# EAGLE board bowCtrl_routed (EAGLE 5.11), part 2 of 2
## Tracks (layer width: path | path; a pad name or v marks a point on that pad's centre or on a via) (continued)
RXIN  (via drill 0.5) (continued)
  Top 0.2: v95.88,23 97.08,23 C31.1 | X4.6 82.33,17.15 81.18,16 74.53,16 74.28,15.75 63.48,15.75 62.48,14.75 46.12,14.75 45.56,15.31 45.56,17.24 44.84,17.24 U$2.37
  Bottom 0.2: R82.1 97.23,23.05 97.23,23 v95.88,23 95.83,22.95 93.78,22.95 93.23,22.4 89.33,22.4 87.23,20.3 87.23,18.5 85.98,17.25 85.98,16.75 85.33,16.1 82.38,16.1 82.38,17.15 X4.6
RXIP  (via drill 0.5)
  Top 0.2: v95.83,25.6 C30.1 | U$2.40 46.33,18.35 46.33,17.2 46.08,16.95 46.08,15.91 46.84,15.15 53.43,15.15 56.53,18.25 83.83,18.25 84.88,17.2 X4.4
  Bottom 0.2: R81.1 97.28,25.6 v95.83,25.6 93.03,22.8 84.93,22.8 84.93,17.2 X4.4
S88_5V  (via drill 0.5)
  Top 1: v8.53,34.7 10.73,36.9 11.83,36.9 X1.1
  Bottom 1: JMP1.2 12.83,33.1 12.83,35.95 11.88,36.9 X1.1 | v8.53,34.7 8.53,22.75 11.83,19.45 X3.1
S88_CLK  (via drill 0.5)
  Top 0.2: v15.08,19.45 15.38,19.75 22.98,19.75 23.33,19.4 27.08,19.4 27.58,19.9 32.51,19.9 32.85,20.24 U$2.25
  Bottom 0.2: v15.08,19.45 15.43,19.8 15.43,22.2 14.43,23.2 X3.4 14.38,23.35 13.38,24.35 13.38,26.95 10.53,29.8 10.53,37.95 11.78,37.95 12.88,39.05 12.88,39.25 14.38,40.75 X1.4
S88_PS  (via drill 0.5)
  Top 0.2: 17.33,25.75 14.43,25.75 X3.6 | 17.33,25.75 18.53,25.75 18.53,23.3 19.73,22.1 26.53,22.1 27.38,21.25 U$2.23 | v17.33,43.25 14.43,43.25 X1.6 | 17.33,25.75 v17.33,25.8
  Bottom 0.2: v17.33,43.25 16.98,42.9 16.98,29.05 17.33,28.7 v17.33,25.8
S88_RAILD  (via drill 0.5)
  Top 0.2: v26.33,23.3 27.93,21.7 29.98,21.7 30.08,21.8 35.38,21.8 35.48,21.7 37.48,21.7 U$2.22 | v26.08,25.65 23.43,28.3 16.58,28.3 | 16.58,28.3 14.43,28.3 X3.8 | v16.58,45.45 14.78,45.45 14.43,45.8 X1.8 | 16.58,28.3 v16.58,28.35
  Bottom 0.2: v26.33,23.3 26.08,23.55 v26.08,25.65 | v16.58,28.35 v16.58,45.45
S88_RST  (via drill 0.5)
  Top 0.2: v13.53,22.2 14.33,22.2 14.83,21.7 26.28,21.7 27.23,20.75 U$2.24 | v7.88,41.05 10.23,43.4 10.68,43.4 11.83,44.55 X1.7 | v7.38,27.6 7.88,27.1 11.83,27.1 X3.7
  Bottom 0.2: v13.53,22.2 12.88,22.85 12.88,26.05 11.88,27.05 X3.7 | v7.88,41.05 7.48,40.65 7.48,27.7 v7.38,27.6
S88_RX  (via drill 0.5)
  Top 0.2: v23.88,24.05 26.68,24.05 28.63,22.1 29.78,22.1 29.93,22.25 33.68,22.25 34.73,23.3 36.28,23.3 36.33,23.25 U$2.19 | v17.73,38.05 17.58,38.2 14.43,38.2 X1.2
  Bottom 0.2: v23.88,24.05 22.33,25.6 20.13,25.6 20.13,35.65 v17.73,38.05
S88_TX  (via drill 0.5)
  Top 0.2: v29.43,22.85 29.63,22.65 33.48,22.65 34.53,23.7 37.48,23.7 U$2.18 | v26.73,20.15 26.38,20.5 14.63,20.5 14.43,20.7 X3.2
  Bottom 0.2: v26.73,20.15 v29.43,22.85
SENSE0  (via drill 0.5)
  Top 0.2: v28.38,42.85 30.58,45.05 31.63,45.05 31.98,44.7 45.63,44.7 45.73,44.6 U$3.28 | v27.18,39.65 16.28,39.65 16.18,39.75 13.03,39.75 11.78,41 v10.73,41 | R2.2 12.23,50.05 v12.28,50.05
  Bottom 0.2: v28.38,42.85 27.18,41.65 v27.18,39.65 | v10.73,41 9.78,41.95 9.78,48.55 R86.1 9.38,49.05 9.38,50.05 v12.28,50.05
SENSE1  (via drill 0.5)
  Top 0.2: v49.23,47.15 47.28,45.2 45.78,45.2 U$3.27 | v50.03,62.05 47.98,64.1 40.03,64.1 37.93,62 37.93,61.1 36.68,61.1 36.63,61.15 v34.08,61.15 | v33.03,57.15 32.68,57.5 16.38,57.5 15.88,57 15.88,53 16.38,53 17.03,52.35 17.03,49 R87.1 11.13,49.05 10.13,50.05 8.68,50.05 v8.03,50.7
  Bottom 0.2: v49.23,47.15 50.03,47.95 v50.03,62.05 | v34.08,61.15 33.03,60.1 v33.03,57.15 | R4.2 8.03,51.25 v8.03,50.7
SENSE2  (via drill 0.5)
  Top 0.2: v46.93,45.95 45.83,45.95 U$3.26 | v42.48,43.95 42.13,44.3 v31.28,44.3 | v31.13,50.8 21.63,50.8 R6.2 21.23,51.1 20.33,50.2 18.38,50.2 v18.18,50.4
  Bottom 0.2: v46.93,45.95 45.03,44.05 45.03,41.45 44.48,40.9 42.48,40.9 v42.48,43.95 | v31.28,44.3 31.13,44.45 v31.13,50.8 | v18.18,50.4 R88.1
SENSE3  (via drill 0.5)
  Top 0.2: v28.78,47.35 29.83,46.3 36.13,46.3 36.38,46.55 45.73,46.55 U$3.25 | 22.53,49.6 21.88,49.6 R89.1 | 22.53,49.6 v27.28,49.6 | v22.53,50 22.53,49.6
  Bottom 0.2: v28.78,47.35 27.28,48.85 v27.28,49.6 | R8.2 20.33,50.5 20.33,50.35 20.63,50.05 22.53,50.05 v22.53,50
SENSE4  (via drill 0.5)
  Top 0.2: v35.68,47.15 U$3.24 | v35.78,50.35 34.88,51.25 R10.2
  Bottom 0.2: v35.68,47.15 35.78,47.25 v35.78,50.35
SENSE5  (via drill 0.5)
  Top 0.2: v35.03,48.85 35.08,48.85 36.23,47.7 45.63,47.7 U$3.23
  Bottom 0.2: v35.03,48.85 32.78,51.1 R12.2
SENSE6  (via drill 0.5)
  Top 0.2: v44.13,48.45 U$3.22 | v44.68,51.4 44.53,51.25 R14.2
  Bottom 0.2: v44.13,48.45 44.68,49 v44.68,51.4
SENSE7  (via drill 0.5)
  Top 0.2: v43.03,48.85 43.38,49.2 45.68,49.2 45.73,49.15 U$3.21
  Bottom 0.2: v43.03,48.85 41.68,50.2 R16.2
SENSE8
  Top 0.2: R18.2 58.08,51.1 56.23,49.25 53.58,49.25 U$3.18
SENSE9  (via drill 0.5)
  Top 0.2: U$3.17 53.48,48.5 57.29,48.5 v57.85,49.06
  Bottom 0.2: v57.85,49.06 56.48,50.43 R20.2
SENSE10
  Top 0.2: R22.2 67.78,51.1 66.88,50.2 64.97,50.2 63.46,51.71 60.7,51.71 58.91,49.91 58.91,48.62 58.03,47.75 53.53,47.75 53.48,47.8 U$3.16
SENSE11  (via drill 0.5)
  Top 0.2: v62.78,47.15 53.48,47.15 U$3.15
  Bottom 0.2: v62.78,47.15 65.93,50.3 R24.2
SENSE12  (via drill 0.5)
  Top 0.2: v67.53,45.05 63.78,45.05 62.28,46.55 53.48,46.55 U$3.14 | v70.53,49.8 70.93,50.2 79.58,50.2 80.48,51.1 R26.2
  Bottom 0.2: v67.53,45.05 68.28,45.8 68.28,47.55 v70.53,49.8
SENSE13  (via drill 0.5)
  Top 0.2: v51.53,47.3 52.83,46 53.33,46 53.43,45.9 U$3.13 | v51.53,55.3 53.78,57.55 59.68,57.55 v62.73,54.5 | v77.48,50.95 70.58,50.95 69.43,49.8 63.73,49.8 63.38,50.15 v63.38,50.33
  Bottom 0.2: v51.53,47.3 v51.53,55.3 | v62.73,54.5 63.38,53.85 v63.38,50.33 | v77.48,50.95 78.88,50.95 R28.2
SENSE14  (via drill 0.5)
  Top 0.2: v52.28,45.35 53.33,45.35 53.43,45.25 U$3.12 | v38.28,78.8 38.33,78.85 83.83,78.85 86.78,75.9 88.28,75.9 v90.68,73.5 | v93.93,54.6 R30.2
  Bottom 0.2: v38.28,78.8 48.98,78.8 51.73,76.05 51.73,73.35 52.28,72.8 v52.28,45.35 | v90.68,73.5 90.68,72 91.98,70.7 92.33,70.7 92.33,67.7 93.93,66.1 v93.93,54.6
SENSE15  (via drill 0.5)
  Top 0.2: v58.58,45.8 55.28,45.8 54.18,44.7 53.58,44.7 U$3.11 | v59.88,47.9 61.23,47.9 61.54,48.21 70.48,48.21 71.42,47.27 82.4,47.27 85.13,50 v87.73,50
  Bottom 0.2: v87.73,50 R32.2 | v58.58,45.8 59.88,47.1 v59.88,47.9
SERV0  (via drill 0.5)
  Top 0.2: LED1.C 6.83,69.85 6.63,69.65 R65.1 4.98,69.6 4.53,69.6 v3.88,68.95 | v32.83,30.95 36.03,27.75 U$2.10 | v26.53,59.45 23.83,62.15 20.78,62.15 18.63,64.3 v1.33,64.3
  Bottom 0.2: v32.83,30.95 29.13,34.65 29.13,45.9 26.53,48.5 v26.53,59.45 | v1.33,64.3 0.88,64.75 0.88,65.95 v3.88,68.95
SERV1  (via drill 0.5)
  Top 0.2: LED3.C 11.73,69.65 R66.1 10.08,69.7 9.28,69.7 9.28,72 10.63,73.35 19.43,73.35 19.43,70.75 19.63,70.55 22.83,70.55 22.83,69.35 23.03,69.15 23.98,69.15 v24.48,68.65 | v24.18,32.85 25.73,31.3 31.28,31.3 35.33,27.25 U$2.11
  Bottom 0.2: v24.18,32.85 22.03,35 22.03,42.75 21.68,43.1 21.38,43.1 21.38,45.1 22.58,46.3 22.58,47.75 24.28,49.45 24.28,62.5 24.48,62.7 v24.48,68.65
SERV2  (via drill 0.5)
  Top 0.2: LED5.C 16.98,69.85 16.78,69.65 R67.1 14.73,69.15 11.83,69.15 v11.03,68.35 | v23.08,32.85 25.03,30.9 30.88,30.9 35.03,26.75 U$2.12 | v16.28,52 13.43,54.85 13.43,58.7 v10.83,58.7
  Bottom 0.2: v16.28,52 16.28,51.2 18.38,49.1 18.38,47.25 18.13,47 18.13,43.1 18.43,43.1 18.78,42.75 18.78,41.25 20.53,39.5 20.53,32.85 v23.08,32.85 | v10.83,58.7 11.03,58.9 v11.03,68.35
SERV3  (via drill 0.5)
  Top 0.2: R68.1 21.88,69.65 22.08,69.85 LED7.C 22.18,69.8 22.28,69.8 v22.28,68.65 | v34.43,26.25 U$2.13 | v37.18,61.85 36.88,62.15 33.93,62.15 31.68,64.4 v21.68,64.4 | v81.47,30.85 81.68,31.06 95.74,31.06 v95.79,31.11 | v20.67,67.01 97.79,67.01 v98.51,67.73
  Bottom 0.2: v34.43,26.25 34.38,26.3 34.38,35.5 35.48,36.6 35.48,45.85 36.58,46.95 36.58,55.05 36.78,55.25 36.78,61.45 v37.18,61.85 | v21.68,64.4 21.23,64.85 21.23,67.01 | 21.23,67.01 21.23,67.6 v22.28,68.65 | 21.23,67.01 v20.67,67.01 | R100.2 81.47,32.75 v81.47,30.85 | v95.79,31.11 95.79,42.43 97.78,44.42 97.78,60.64 99.77,62.63 99.77,66.47 v98.51,67.73
SERV4  (via drill 0.5)
  Top 0.2: R69.1 29.98,69.65 LED9.C 31.18,68.85 34.88,68.85 v35.48,68.25 | v41.58,36.5 41.83,36.5 U$2.95
  Bottom 0.2: v41.58,36.5 40.03,38.05 40.03,42.15 39.28,42.9 39.28,56.4 37.88,57.8 37.88,61.45 37.93,61.5 37.93,65.8 v35.48,68.25
SERV5  (via drill 0.5)
  Top 0.2: LED11.C 35.23,69.85 35.03,69.65 R70.1 33.38,69.7 32.58,69.7 32.58,72.8 32.03,73.35 28.83,73.35 27.53,72.05 27.53,70.4 v26.93,69.8 | v40.48,36.5 41.23,35.75 41.33,35.75 U$2.96 | v39.28,38.8 39.18,38.9 v31.28,38.9 | v30.28,51.55 25.08,56.75 v25.03,56.75
  Bottom 0.2: v40.48,36.5 39.28,37.7 v39.28,38.8 | v30.28,51.55 30.28,44.05 31.28,43.05 v31.28,38.9 | v25.03,56.75 25.38,57.1 25.38,63.75 26.93,65.3 v26.93,69.8
SERV6  (via drill 0.5)
  Top 0.2: LED13.C 40.13,69.65 R71.1 38.63,69.6 v38.63,68.5 | v39.38,36.5 39.83,36.05 U$2.99 | v38.53,56.05 38.53,57.35 v39.43,57.35 39.18,57.4 40.53,58.75 42.58,58.75 42.58,59.3 44.43,61.15 50.23,61.15 51.13,62.05 60.43,62.05 63.63,58.85 71.18,58.85 v71.28,58.75 | v74.98,44.9 73.47,46.41 v71.29,46.41
  Bottom 0.2: v39.38,36.5 38.53,37.35 v38.53,56.05 | v39.43,57.35 39.38,57.4 39.38,59.15 38.88,59.65 38.88,68.25 v38.63,68.5 | R99.2 78.03,35.75 78.03,35.9 77.73,36.2 76.18,36.2 75.68,36.7 74.98,36.7 v74.98,44.9 | v71.29,46.41 v71.28,46.42 71.83,46.97 71.83,58.2 v71.28,58.75
SERV7  (via drill 0.5)
  Top 0.2: LED15.C 45.38,69.85 45.18,69.65 R72.1 43.13,69.15 40.73,69.15 39.14,67.56 37.81,67.56 v37.43,67.94 | v38.08,36.5 38.08,35.35 U$2.100 | v37.53,57.05 v38.63,58.15
  Bottom 0.2: v38.08,36.5 37.43,37.15 37.43,37.5 36.98,37.95 36.98,54.85 37.53,55.4 v37.53,57.05 | v38.63,58.15 38.33,58.45 38.33,67.04 v37.43,67.94
SERV8  (via drill 0.5)
  Top 0.2: R73.1 53.28,69.65 53.48,69.85 LED17.C 53.58,69.9 53.98,69.9 v53.98,71.05 | v61.68,27.75 53.23,27.75 U$2.66 | v61.83,59.55 60.08,61.3 v57.38,61.3
  Bottom 0.2: v61.68,27.75 61.83,27.9 v61.83,59.55 | v57.38,61.3 55.88,62.8 55.88,67.55 54.23,69.2 54.23,70.8 v53.98,71.05
SERV9  (via drill 0.5)
  Top 0.2: R74.1 58.38,69.65 LED19.C 59.78,68.65 v63.78,68.65 | v59.53,32.75 59.88,32.4 74.23,32.4 74.98,33.15 74.98,33.95 v75.13,33.95 | U$2.67 53.23,28.2 58.63,28.2 v58.93,28.5 | v70.08,41.7 70.08,41 v57.43,41
  Bottom 0.2: v75.13,33.95 79.73,33.95 79.73,36.3 R98.2 | v63.78,68.65 68.33,64.1 70.6,64.1 71.42,63.28 71.42,59.89 72.23,59.08 72.23,45.9 70.08,43.75 v70.08,41.7 | v57.43,41 57.58,40.85 57.58,35.2 59.48,33.3 59.48,32.8 v59.53,32.75 59.53,31.85 58.93,31.25 v58.93,28.5
SERV10  (via drill 0.5)
  Top 0.2: R75.1 63.43,69.65 63.63,69.85 LED21.C 63.73,69.8 v64.88,68.65 | v56.03,29.45 55.68,29.8 54.08,29.8 54.03,29.75 53.23,29.75 U$2.70 | v58.43,32.95 59.53,34.05 70.58,34.05 71.48,34.95 71.68,34.95 72.43,35.7 72.43,40.05 74.23,40.05 74.98,40.8 74.98,42.25 v76.33,43.6
  Bottom 0.2: v56.03,29.45 58.43,31.85 v58.43,32.95 | v64.88,68.65 64.88,68.6 71.93,68.6 73.79,66.74 73.79,47.86 76.33,45.32 v76.33,43.6
SERV11  (via drill 0.5)
  Top 0.2: R76.1 68.53,69.65 LED23.C 68.83,69.8 69.78,68.85 84.08,68.85 v84.78,68.15 | U$2.71 53.23,30.2 58.83,30.2 59.83,31.2 64.38,31.2 66.28,29.3 78.57,29.3 80.33,31.06 80.33,32.84 v84.51,32.84
  Bottom 0.2: v84.51,32.84 84.78,33.11 v84.78,68.15
SERV12  (via drill 0.5)
  Top 0.2: LED25.C 76.28,69.85 76.08,69.65 R77.1 74.48,69.6 v73.33,69.6 | v43.38,31.45 43.38,34.05 U$2.92 | v42.73,21.3 39.58,21.3 37.96,19.68 35.71,19.68 33.23,17.2 v25.83,17.2 | v25.83,13.9 27.53,12.2 35.33,12.2 36.43,11.1 36.43,9.65 36.03,9.65 35.28,8.9 35.28,7.35 38.48,7.35 38.93,6.9 38.93,5.1 v38.08,5.1 | v55.18,4.6 55.48,4.9 56.93,4.9 57.78,4.05 v57.78,3.7 | v81.43,23.15 80.53,22.25 64.93,22.25 63.18,20.5 v57.48,20.5
  Bottom 0.2: v43.38,31.45 44.03,30.8 44.03,22.6 v42.73,21.3 | v25.83,13.9 v25.83,17.2 | v38.08,5.1 55.18,5.1 v55.18,4.6 | v57.78,3.7 57.68,3.8 57.68,20.3 v57.48,20.5 | v81.43,23.15 82.43,24.15 82.43,42.5 81.68,43.25 80.63,43.25 | 80.63,43.25 79.73,43.25 79.73,40.45 R97.2 | 80.63,43.25 80.63,45.65 81.13,46.15 81.13,50 76.12,50 74.72,51.4 74.72,68.21 v73.33,69.6
SERV13  (via drill 0.5)
  Top 0.2: LED27.C 81.38,69.85 81.18,69.65 R78.1 79.53,69.7 78.73,69.7 78.73,72.75 78.13,73.35 38.63,73.35 37.68,72.4 37.68,69.35 35.83,67.5 31.57,67.5 v31.09,67.98 | v42.78,36.5 43.83,36.5 U$2.91 | v40.78,38.8 39.93,39.65 v34.33,39.65 | v33.08,49.3 32.33,50.05 v28.78,50.05
  Bottom 0.2: v42.78,36.5 40.78,38.5 v40.78,38.8 | v34.33,39.65 33.53,40.45 33.53,48.85 v33.08,49.3 | v28.78,50.05 28.68,50.15 28.68,65.45 31.09,67.86 v31.09,67.98
SERV14  (via drill 0.5)
  Top 0.2: LED29.C 86.28,69.65 R79.1 84.63,69.7 83.83,69.7 83.83,72.75 82.83,73.75 68.63,73.75 66.48,75.9 50.18,75.9 v49.93,76.15 | v36.68,36.9 37.03,37.25 44.33,37.25 U$2.90 | v36.23,45.45 36.58,45.8 v44.58,45.8
  Bottom 0.2: v36.68,36.9 36.23,37.35 v36.23,45.45 | v44.58,45.8 48,49.22 48,54.54 48.88,55.42 48.88,62.15 49.98,63.25 49.98,67.85 51.23,69.1 51.23,75.5 50.58,76.15 v49.93,76.15
SERV15  (via drill 0.5)
  Top 0.2: LED31.C 91.53,69.85 91.33,69.65 90.31,69.65 | 90.31,69.65 R80.1 | v45.08,36.5 44.88,36.5 44.88,34.1 U$2.89 | v80.38,49.25 v85.53,54.4 | v77.01,48.2 71.68,48.2 71.04,48.84 62.46,48.84 62.26,49.04 v59.86,49.05 | v53.69,52.02 48.99,52.02 v48.96,52.05 | v89.77,68.27 89.77,69.11 90.31,69.65
  Bottom 0.2: v45.08,36.5 47.78,39.2 47.78,39.75 46.68,40.85 46.13,40.85 45.53,41.45 45.53,43.9 46.53,44.9 47.03,44.9 47.78,45.65 47.78,48.4 48.96,49.58 v48.96,52.05 | R96.2 79.33,42.3 79.33,48.2 | 79.33,48.2 v80.38,49.25 | v85.53,54.4 85.28,54.65 85.28,63.2 86.78,64.7 88.88,64.7 88.88,67.38 v89.77,68.27 | v77.01,48.2 79.33,48.2 | v53.69,52.02 54.26,51.45 54.26,50.59 57.25,47.6 58.41,47.6 v59.86,49.05
SPI_A0  (via drill 0.5)
  Top 0.2: v37.18,64.4 37.28,64.5 66.08,64.5 69.43,61.15 v72.86,61.15 | v69.83,26.3 68.98,25.45 v68.33,25.45 | v68.33,9.1 68.33,7.55 65.63,7.55 v65.18,7.1 | U$2.29 40.83,19.15 39.03,19.15 38.47,18.59 38.47,18.37 38.1,18 v35.23,18 | v35.13,34.75 30.68,34.75 v29.93,35.5
  Bottom 0.2: v35.23,18 35.13,18.1 35.13,25.85 35.18,25.9 35.18,28.6 35.13,28.65 v35.13,34.75 | v37.18,64.4 30.18,64.4 29.08,63.3 29.08,56.35 29.53,55.9 29.53,39.5 29.53,38.3 29.53,35.9 v29.93,35.5 | v69.83,26.3 69.83,26.75 71.08,26.75 72.68,28.35 72.68,43.8 73.23,44.35 73.23,60.78 v72.86,61.15 | v68.33,25.45 v68.33,9.1 | v65.18,7.1 64.88,6.8 64.88,4.1 64.18,3.4 U$1.38
SPI_CS_ADC  (via drill 0.5)
  Top 0.2: v55.38,33.7 54.58,32.9 52.43,32.9 52.43,30.95 52.63,30.75 U$2.72 | v51.63,40.55 51.63,42.8 46.38,42.8 46.23,42.65 45.78,42.65 U$3.31
  Bottom 0.2: v55.38,33.7 55.33,33.75 55.33,36.8 54.23,37.9 54.23,38.35 52.03,40.55 v51.63,40.55
SPI_CS_DOGM  (via drill 0.5)
  Top 0.2: v55.63,30.95 55.38,31.2 53.23,31.2 U$2.73 | v59.73,10.1 61.73,8.1 67.33,8.1 v67.53,8.3
  Bottom 0.2: v55.63,30.95 55.28,30.6 55.28,23.8 59.73,19.35 v59.73,10.1 | v67.53,8.3 68.33,7.5 68.33,5.75 69.18,4.9 69.18,3.4 U$1.40
SPI_CS_SD  (via drill 0.5)
  Top 0.2: v66.63,30.05 65.08,31.6 58.98,31.6 58.88,31.7 53.23,31.7 U$2.74
  Bottom 0.2: JP33.8 63.93,9.1 64.88,10.05 64.88,12.6 66.23,12.6 67.43,13.8 67.43,17.85 66.63,18.65 v66.63,30.05
SPI_SCLK  (via drill 0.5)
  Top 0.2: 40.38,18.35 U$2.28 40.38,18.3 40.38,17.6 v40.83,17.15 | JP33.7 66.43,9.1 65.43,10.1 64.08,10.1 63.33,10.85 v61.68,10.85 57.63,10.85 56.98,11.5 45.33,11.5 v45.03,11.2 | v50.88,42.05 45.83,42.05 U$3.32 | v55.48,44.8 63.43,44.8 64.18,44.05 v64.28,44.05
  Bottom 0.2: v50.88,42.05 53.63,44.8 v55.48,44.8 | v64.28,44.05 63.93,43.7 63.93,39.65 64.38,39.2 64.38,25.15 65.73,23.8 65.73,20.95 64.83,20.05 63.78,20.05 61.53,17.8 61.53,10.85 | 61.53,10.85 61.53,8.15 61.98,7.7 61.98,3.75 61.63,3.4 U$1.37 | v61.68,10.85 61.53,10.85 | v40.83,17.15 45.03,12.95 v45.03,11.2
SPI_SDI  (via drill 0.5)
  Top 0.2: v37.98,10.1 41.53,6.55 56.03,6.55 59.03,3.55 59.03,3.4 U$1.36 58.68,4 60.28,5.6 65.48,5.6 66.38,6.5 JP33.9 66.48,6.6 67.98,6.6 v69.08,7.7 | U$2.31 41.83,19.2 41.38,19.2 41.03,19.55 38.78,19.55 38.09,18.86 v37.7,18.86 | v48.53,41.3 45.78,41.3 U$3.33 | v71.5,67.82 v51.15,67.82
  Bottom 0.2: v48.53,41.3 50.78,43.55 50.78,67.45 v51.15,67.82 | v69.08,7.7 69.08,29.3 71.13,29.3 72.28,30.45 72.28,44 72.63,44.35 72.63,59.76 72.03,60.36 72.03,63.55 71.5,64.08 v71.5,67.82 | v37.98,10.1 37.98,12.25 37.44,12.79 37.44,18.6 v37.7,18.86
SPI_SDO  (via drill 0.5)
  Top 0.2: 47.68,40.55 47.68,40.65 45.78,40.65 U$3.34 | 47.68,40.55 47.68,38.9 46.33,37.55 45.13,37.55 45.03,37.65 36.33,37.65 35.98,37.3 26.78,37.3 25.63,36.15 19.03,36.15 18.38,35.5 v15.83,35.5 | 41.33,18.35 U$2.30 41.33,18.25 41.33,17.85 41.58,17.6 41.58,16.4 32.83,16.4 32.78,16.35 32.78,14.65 15.78,14.65 15.28,15.15 v15.28,16.39 | v61.23,7.35 63.13,7.35 63.88,6.6 JP33.10 | v54.63,44.05 v56.88,44.05 | v49.63,41.3 48.88,40.55 47.68,40.55
  Bottom 0.2: v15.83,35.5 15.83,27.75 15.93,27.75 16.43,27.25 16.43,25.5 16.68,25.25 16.68,19.6 16.43,19.35 16.43,17.54 v15.28,16.39 | v61.23,7.35 60.93,7.65 60.93,19.8 56.88,23.85 56.88,26.55 57.63,27.3 58.83,27.3 59.73,28.2 59.73,28.7 60.93,29.9 60.93,33.75 59.13,35.55 59.13,38.2 58.18,39.15 58.18,41.35 56.88,42.65 v56.88,44.05 | v54.63,44.05 51.88,41.3 v49.63,41.3
TCK  (via drill 0.5)
  Top 0.2: v49.68,36.45 49.38,36.45 49.38,34.1 U$2.80 | v54.58,35.85 55.23,35.2 v67.68,35.2
  Bottom 0.2: v49.68,36.45 50.93,37.7 52.58,37.7 52.58,36.85 52.63,36.8 52.63,36.55 53.33,35.85 v54.58,35.85 | v67.68,35.2 71.28,31.6 JTAG1.9
TDI  (via drill 0.5)
  Top 0.2: v46.98,29.95 50.33,33.3 50.33,34.05 U$2.78 | v69.83,20.9 64.98,20.9 63.43,19.35 52.33,19.35 51.13,20.55 50.48,20.55 47.98,23.05 v46.98,23.05
  Bottom 0.2: v46.98,23.05 v46.98,29.95 | v69.83,20.9 70.28,21.35 70.28,24.75 71.28,25.75 JTAG1.5
TDO  (via drill 0.5)
  Top 0.2: v51.88,36.45 51.38,35.95 50.88,35.95 50.88,34.1 U$2.77 | v54.58,34.75 54.88,34.45 69.83,34.45 71.28,35.9 JTAG1.13
  Bottom 0.2: v51.88,36.45 52.23,36.1 52.48,36.1 53.83,34.75 v54.58,34.75
TMS  (via drill 0.5)
  Top 0.2: v58.33,37.85 56.88,37.85 56.48,37.45 51.78,37.45 50.03,35.7 49.88,35.7 49.88,34.1 U$2.79 | JTAG1.7 71.28,28.35 66.63,28.35 64.53,30.45 v60.18,30.45
  Bottom 0.2: v60.18,30.45 60.28,30.55 60.28,33.6 58.33,35.55 v58.33,37.85
TXON  (via drill 0.5)
  Top 0.2: U$2.46 49.38,18.4 49.38,19.3 49.48,19.4 49.48,20.1 48.63,20.95 47.98,20.95 46.23,22.7 46.23,23.4 46.93,24.1 48.18,24.1 52.53,19.75 63.18,19.75 65.08,21.65 86.17,21.65 86.17,20.8 | 86.13,19.75 X4.3 86.17,20.8 | C33.1 97.08,20.7 96.98,20.8 v95.88,20.8 86.17,20.8
  Bottom 0.2: v95.88,20.8 97.23,20.8 R84.1
TXOP  (via drill 0.5)
  Top 0.2: v47.83,15.9 47.83,18.35 U$2.43 | v47.68,13.2 48.03,13.55 62.58,13.55 63.33,12.8 66.43,12.8 68.48,14.85 75.28,14.85 75.93,15.5 77.18,15.5 77.43,15.25 84.48,15.25 86.38,17.15 86.38,18.65 87.63,18.65 88.68,19.7 X4.1 88.78,19.7 95.73,19.7 95.88,19.55 | 95.88,19.55 97.03,18.4 C32.1 | 95.88,19.55 v96.03,19.7
  Bottom 0.2: v47.83,15.9 47.68,15.75 v47.68,13.2 | v96.03,19.7 R83.1
V2_5  (via drill 0.6)
  Top 0.254: U$2.14 39.07,25.74 v39.18,25.85 | U$2.7 38.94,29.24 40.18,28 | U$2.62 v51.68,25.75 | 45.34,21.34 U$2.38 | 45.34,31.59 U$2.88
  Top 0.61: 40.18,25.85 40.18,28
  Top 1.016: v39.18,25.85 40.18,25.85 40.83,25.85 C22.+ | C22.+ 45.34,21.34 | 44.14,25.75 v51.68,25.75 | C22.+ 44.14,25.75 | 45.34,31.59 44.14,30.39 44.14,25.75
  Bottom 1.016: C21.1 v39.18,25.85 | 42.18,25 42.53,24.65 C22.+ | v51.68,25.75 52.03,25.85 C29.1
  other vias: 42.53,24.14
V3_3  (via drill 0.5, 0.6)
  Top 0.2: U$2.36 44.34,16.74 v44.76,16.32
  Top 0.254: U$2.83 U$2.84 47.34,34.84 v46.93,35.25 | U$2.3 38.17,31.24 39.31,32.38 40.34,33.41 U$2.98 | U$2.8 36.19,28.74 v35.93,29 | U$2.93 42.84,35.09 v42.68,35.25 | U$2.81 48.84,34.84 v48.43,35.25 | U$2.68 54.17,28.74 v54.43,29 | U$2.56 54.17,22.74 v54.43,23 | U$2.32 42.34,17.19 v42.43,17.1 | U$2.44 48.34,17.69 v48.93,17.1 | U$2.20 36.17,22.74 v35.93,22.5 | U$3.5 C55.1 | U$3.29 43.74,43.91 C54.1 | U$3.36 43.93,39.36 43.72,39.36 C56.1 | U$4.2 66.43,39.12 v66.43,38.25
  Top 0.406: v43.93,38.85 43.93,39.36
  Top 1: v85.58,29.8 v95.38,29.8 95.43,29.35 95.43,26.85 v90.18,21.6 | v33.53,18.65 33.38,18.8 30.28,18.8 OK1.8 29.83,18.6 v24.93,18.6 | v15.03,31.3 15.68,30.65 v17.78,30.65 | v19.33,25.45 19.33,23.65 19.88,23.65 v20.63,22.9 | v34.88,14.2 v36.48,14.2 36.93,14.45 37.88,15.4 42.38,15.4 42.38,17 v42.43,17.1 | U$1.34 54.03,3.4 56.48,3.4 U$1.35 | v56.13,40.6 55.03,40.6 C55.1 | v56.78,36.7 64.83,36.7 66.33,38.2 v66.43,38.25 | 62.33,12 57.63,12 v56.88,12.75 | 62.33,12 63.53,12 63.88,11.65 JP33.6 | v76.38,20.6 74.83,19.05 v64.28,19.05 | 62.33,12 v62.33,12.6
  Top 1.016: v37.68,33.25 38.43,33.25 39.31,32.38 42.43,29.25 C48.+ | C56.1 C54.1
  Bottom 0.2: 44.92,17.1 44.72,16.9 | 44.41,17.1 44.85,16.66
  Bottom 0.254: 36.43,29 v35.93,29 | C20.+ 92.18,7.75 92.43,8 92.43,12 R101.2 | v35.93,22.5 36.43,23 36.43,23.25 | v66.43,38.25 68.98,38.25 C57.1
  Bottom 1: 85.97,11.67 86.43,12.1 86.43,12.15 v86.73,12.45 88.13,13.85 C34.1 87.88,14.3 87.48,14.7 87.48,17.15 X4.2 87.93,17.4 90.18,17.4 v90.18,21.6 | R83.2 98.93,18.5 98.93,20.25 R84.2 98.98,20.8 98.98,23.05 R82.2 98.98,23.5 R81.2 98.78,25.95 98.63,26.1 98.63,26.55 v95.38,29.8 | 83.28,21.2 83.58,21.2 83.58,19.75 X4.5 | 83.28,21.2 80.48,21.2 80.03,20.75 78.83,20.75 C35.1 78.28,20.6 v76.38,20.6 | 83.28,29.8 R116.1 | 83.28,21.2 83.28,29.8 | 83.28,29.8 v85.58,29.8 | v33.53,18.65 33.53,15.75 C68.2 34.13,15.5 34.88,14.75 v34.88,14.2 | JMP1.3 15.03,32.6 v15.03,31.3 | v17.78,30.65 19.33,29.1 v19.33,25.45 | v24.93,18.6 v20.63,22.9 | R110.2 28.93,16.35 28.93,17.5 OK1.8 | v56.13,40.6 56.53,40.2 56.53,36.7 | 56.53,36.7 56.53,33.2 55.88,32.55 54.43,32.55 | 56.53,36.7 v56.78,36.7 | 43.93,35.25 v43.93,38.85 | U$1.35 56.63,3.5 56.63,5 56.88,5.25 v56.88,9.5 v56.88,12.75 56.88,15.2 53.38,18.7 | v36.48,14.2 36.48,20.85 36.43,20.9 36.43,22.85 | v64.28,19.05 62.33,17.1 v62.33,12.6 | v44.76,16.32 44.76,17.07 44.73,17.1
  Bottom 1.016: C41.1 C46.1 47.93,34 47.93,35.25 | C53.1 C40.1 41.68,34 41.68,35.25 | 36.43,27.15 C44.1 | 36.43,27.15 36.43,29 36.43,31.25 37.03,31.85 C43.1 v37.68,33.25 37.68,35.25 41.68,35.25 | C49.1 36.43,22.85 36.43,23.25 36.43,27.15 | C48.+ 42.93,29.65 42.93,30 | 41.68,35.25 v42.68,35.25 43.93,35.25 v46.93,35.25 | v46.93,35.25 47.28,35.25 | v46.93,35.25 47.93,35.25 | 47.93,35.25 v48.43,35.25 52.18,35.25 54.43,33 54.43,32.55 54.43,30.4 | C50.1 54.43,22.6 v54.43,23 | 54.43,27.4 v54.43,23 | 54.43,27.4 C52.1 | 54.43,30.4 C51.1 | 54.43,30.4 v54.43,29 54.43,27.4 | C42.1 45.08,17.1 44.92,17.1 44.73,17.1 44.41,17.1 v42.43,17.1 42.03,17.1 C45.1 | v54.43,23 54.43,19.75 53.38,18.7 51.78,17.1 v48.93,17.1 48.48,17.1 C47.1
  Bottom 1.27: 85.97,10.76 IC4.3 88.38,7.89 C28.1 v91.38,7.85 91.41,7.85 C20.+ | 85.97,10.76 D37.A | 85.97,11.67 85.97,10.76
  other vias: 42.53,29.25
  pour Top: 0.93,0.5 99.93,0.5 99.93,50 0.93,50
V5_0  (via drill 0.5, 0.6)
  Top 1: v11.33,31.3 10.68,31.95 4.02,31.95 3.15,31.08 | v13.78,67.2 2.33,67.2 JP36.2 | v1.83,16.8 1.83,18.3 2.93,19.4 2.93,20.74 2.21,21.46 2.21,28.63 3.15,29.57 3.15,31.08 | 3.15,31.08 1.18,33.05 1.18,36 v11.63,46.45
  Top 1.27: D38.A 5.43,9.75 v5.43,11.75
  Bottom 1: JMP1.1 11.33,32.6 v11.33,31.3 | v1.83,16.8 5.23,13.4 5.23,12.35 v5.42,11.75 | v13.78,67.2 14.73,66.25 14.73,49.55 v11.63,46.45
  Bottom 1.016: C19.+ 75.28,8.72
  Bottom 1.27: IC3.OUT 8.01,3.87 C26.1 5.42,8.92 C18.+ v5.42,11.75 v5.43,11.75 | D37.C 81.35,10.72 IC4.1 81.06,7.89 C27.1 77.98,5.78 C19.+
  Bottom 1.422: IC3.OUT 8.25,1.25 70.68,1.25 72.43,3 72.43,7.75 72.88,8.2 C19.+ 75.81,10.75 R103.2
V5_0S
  Top 1: JP36.1 2.33,73.9 3.33,74.9 7.58,74.9 JP1.2 | C4.1 25.68,75.65 24.98,74.95 22.88,74.95 JP4.2 | JP2.2 12.73,74.95 17.73,74.95 JP3.2 | C12.1 72.03,75.85 71.13,74.95 69.53,74.95 JP12.2 | JP38.1 96.88,72.4 94.88,72.4 92.38,74.9 92.33,74.9 JP16.2 | JP8.2 46.18,74.95 54.23,74.95 JP9.2
  Bottom 1: 12.68,75.85 10.18,75.85 C1.1 9.73,75.55 7.63,75.55 7.63,74.95 JP1.2 | 12.68,75.85 12.68,74.95 JP2.2 | C2.1 15.23,75.9 13.13,75.9 12.68,75.85 | 24.86,73.87 23.28,75.45 JP4.2 22.83,74.95 22.83,75.85 20.33,75.85 C3.1 19.83,75.65 19.83,74.95 17.78,74.95 JP3.2 | 24.86,73.87 26.98,71.75 C23.+ | 33.48,75.85 35.98,75.85 | 35.98,75.85 35.98,74.95 JP6.2 | 33.48,75.85 C5.1 | 35.98,75.85 36.43,75.9 38.53,75.9 C6.1 39.03,75.9 40.68,75.9 41.13,75.85 | 41.13,75.85 43.63,75.85 C7.1 44.08,75.85 46.18,75.85 | 41.13,75.85 41.13,74.95 JP7.2 | 46.18,75.85 48.68,75.85 C8.1 | 46.18,75.85 46.18,74.95 JP8.2 | 59.33,75.85 56.83,75.85 C9.1 56.38,75.55 56.38,74.95 54.28,74.95 JP9.2 | 59.33,75.85 JP10.2 | 59.33,75.85 59.78,75.9 61.83,75.9 C10.1 62.38,75.75 64.18,75.75 64.18,75.4 JP11.2 64.43,74.95 66.53,74.95 66.53,75.55 C11.1 66.98,75.85 69.48,75.85 69.48,74.95 JP12.2 69.93,75.2 C24.+ 73.68,72.15 76.58,75.05 JP13.2 77.08,74.95 79.13,74.95 79.13,75.65 C13.1 79.63,75.85 82.13,75.85 | 82.13,75.85 82.13,74.95 JP14.2 | 82.13,75.85 82.58,75.9 84.68,75.9 C14.1 85.18,75.75 86.98,75.75 86.98,75.4 JP15.2 87.23,74.95 89.43,74.95 89.43,75.45 C15.1 89.78,75.85 92.28,75.85 | 92.28,75.85 92.28,74.95 JP16.2 | C16.1 94.83,75.9 92.73,75.9 92.28,75.85 | 33.48,75.85 31.85,75.85 JP5.2 25.92,74.93 24.86,73.87
  pour Top: 99.93,79.5 0.93,79.5 0.93,51 99.93,51
VIN
  Top 1.27: D33.A JP40.2
VING
  Top 1.27: 13.33,6.67 C25.1 | IC3.IN 13.33,6.67 | 13.33,6.67 13.33,9.75 D38.C D33.C
  Bottom 1.27: C17.+ 13.33,5.01 IC3.IN
VLEDL  (via drill 0.5)
  Top 0.2: X4.A1 78.83,24.6 79.88,25.65 86.13,25.65 87.18,24.6 X4.A2 | R117.2 95.93,47.1 v90.33,47.1 89.13,47.1 89.03,47 83.88,47 v83.78,47.1 | v15.18,68.5 16.63,68.5 v16.78,68.65 17.53,67.9 v29.53,67.9 | v57.78,68.65 v53.68,68.65 53.63,68.7 45.68,68.7 v45.63,68.65
  Bottom 0.2: R116.2 81.58,44.9 v83.78,47.1 83.78,69 | v90.33,47.1 90.98,46.45 90.98,23.3 88.48,23.3 87.23,24.55 X4.A2 | R36.2 21.98,69.85 21.58,69.45 21.58,69 17.78,69 R35.2 16.78,69.71 v16.78,68.65 | 14.38,69.25 14.38,69.2 14.18,69 11.88,69 11.88,69.85 R34.2 | 14.38,69.25 14.38,73.35 11.63,73.35 10.63,72.35 10.63,69 7.63,69 6.78,69.85 R33.2 | v15.18,68.5 14.43,69.25 14.38,69.25 | 45.28,69 41.13,69 40.28,69.85 R39.2 40.18,69.8 37.68,69.8 37.68,69.15 37.53,69 35.13,69 35.08,68.95 | 45.28,69 45.28,69.85 R40.2 | 30.78,69.15 30.98,68.95 35.08,68.95 | 30.78,69.15 R37.2 | 35.08,68.95 35.08,69.8 35.13,69.85 R38.2 | v53.68,68.65 53.68,69.6 53.43,69.85 R41.2 | R42.2 58.48,69.35 v57.78,68.65 57.83,68.6 62.28,68.6 63.53,69.85 R43.2 63.48,69.9 62.78,70.6 62.78,72.8 63.33,73.35 67.83,73.35 67.83,70.65 68.58,69.9 R44.2 68.68,69.85 69.53,69 72.58,69 72.58,69.95 72.98,70.35 76.18,70.35 76.18,69.85 R45.2 76.28,69.8 77.08,69 81.23,69 81.23,69.8 R46.2 81.33,69.85 82.18,69 83.78,69 | 85.58,69 86.38,69 R47.2 | 83.78,69 85.58,69 | R48.2 91.43,69.85 88.88,72.4 88.88,72.8 88.33,73.35 85.58,73.35 85.58,69 | 45.28,69 v45.63,68.65 | v29.53,67.9 30.78,69.15
XTAL1  (via drill 0.5)
  Top 0.2: v34.38,24.95 34.58,24.75 U$2.16 | 33.78,8.85 v35.68,10.75 | 33.78,8.85 C37.1 | v28.38,10.75 30.23,8.9 33.73,8.9 33.78,8.85
  Bottom 0.2: v34.38,24.95 34.48,24.85 34.48,16.35 35.68,15.15 v35.68,10.75 | v28.38,10.75 24.88,7.25 Q1.2
XTAL2  (via drill 0.5)
  Top 0.2: v33.48,24.2 37.48,24.2 U$2.17 | v37.08,9.2 C36.1
  Bottom 0.2: v37.08,9.2 35.18,7.3 34.58,7.3 Q1.1 34.48,7.25 32.73,9 32.73,19.35 33.48,20.1 v33.48,24.2

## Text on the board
Top: S88R | TOP | . | . | . | + | S88T | - | AWA2011 | bowCtrl V1.0
Bottom: BOTTOM | AWA2011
